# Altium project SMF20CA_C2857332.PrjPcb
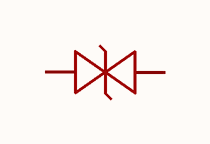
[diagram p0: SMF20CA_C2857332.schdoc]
1 sheet, 1 parts. Net scope: global (net labels, ports and power ports of the same name join across sheets).

## Sheet SMF20CA_C2857332.schdoc
size 127 x 101 mm

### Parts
D?  smf20ca_c2857332  [SMF_L2.9-W1.9-LS3.9-BI]  (value not drawn)

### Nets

Not connected (* = marked no-connect by the designer): D? 1(C) 2(A)

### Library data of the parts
D? = smf20ca_c2857332: 极性:双向;反向截止电压(Vrwm):20V;钳位电压:32.4V;峰值脉冲电流(Ipp):6.2A;峰值脉冲功率(Ppp):200W@10/1000us;击穿电压(VBR):22.2V;; Manufacturer: JSMSEMI(杰盛微); AddInBom: yes; ModelId: 9b190ad72b2a4f2384918ea07687d3cf; ModelName: DO-219AB_L2.8-W1.8-H1.0-LS3.7; ModelTransform: 145.669,70.866,0,0,0,0,0,0,0; Polarity: 双向; Reverse Stand-Off Voltage (Vrwm): 20V; Clamping Voltage: 32.4V; Peak Pulse Current (Ipp): 6.2A; Voltage - Breakdown: 22.2V; Reverse Leakage Current (Ir): 1uA; Number of Channels: 单路; Type: TVS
